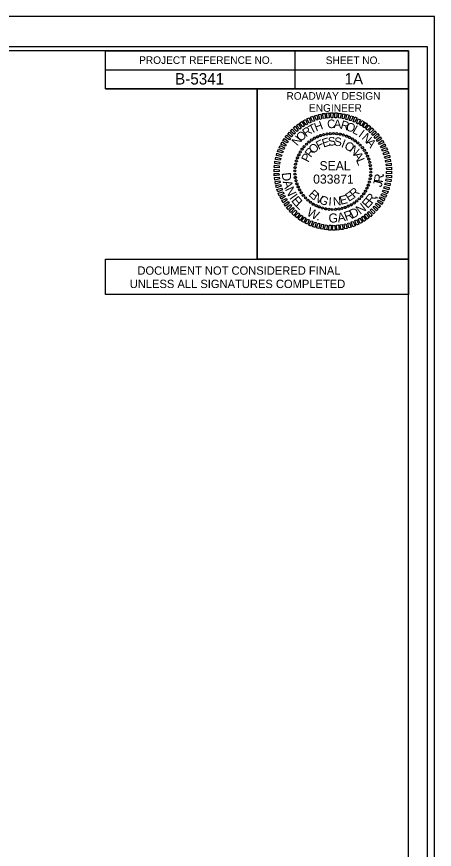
# Model space of a CAD drawing. Extents: x 1974126 to 1975810, y 438878 to 442173.
# Drawn here: x 1975533 to 1975809, y 441624 to 442173 of the extents above; entities that cross this region are included whole.
import ezdxf

# ---------------------------------------------------------------- set-up
doc = ezdxf.new("R2010")
doc.units = 0
for name, color, linetype in [('Sheet Cutting Line CELL', 7, 'Continuous'), ('Sheet Data Field CELL', 7, 'Continuous'), ('Sheet Plan CELL', 7, 'Continuous'), ('Sheet Plot Border Inside CELL', 7, 'Continuous'), ('Sheet Plot Border Outside CELL', 7, 'Continuous'), ('Sheet Professional Seal CELL', 7, 'Continuous'), ('Sheet Sticker Exception Certification CELL', 7, 'Continuous')]:
    doc.layers.add(name, color=color, linetype=linetype)

msp = doc.modelspace()

# ---------------------------------------------------------------- linework, layer by layer
at = {"layer": 'Sheet Cutting Line CELL'}
msp.add_line((1975809.14, 442173.29), (1974125.64, 442173.29), dxfattribs=at)
at = {"layer": 'Sheet Plan CELL'}
for p, q in [((1975717.14, 442150.74), (1975717.14, 442125.74)), ((1975592.09, 442138.24), (1975792.14, 442138.24)), ((1975592.09, 442125.74), (1975792.14, 442125.74)), ((1975592.09, 442125.74), (1975792.14, 442125.74)), ((1975692.14, 442125.74), (1975692.14, 442013.29))]:
    msp.add_line(p, q, dxfattribs=at)
for points in [[(1975792.14, 442150.79), (1974292.14, 442150.79), (1974292.14, 441100.79), (1975792.14, 441100.79)], [(1975592.09, 442150.79), (1975792.14, 442150.79), (1975792.14, 442125.74), (1975592.09, 442125.74)], [(1975692.14, 442125.74), (1975792.14, 442125.74), (1975792.14, 442013.24), (1975692.14, 442013.24)]]:
    msp.add_lwpolyline(points, close=True, dxfattribs=at)
at = {"layer": 'Sheet Plot Border Inside CELL'}
msp.add_lwpolyline([(1974138.64, 441098.29), (1975804.64, 441098.29), (1975804.64, 442153.29), (1974138.64, 442153.29)], close=True, dxfattribs=at)
at = {"layer": 'Sheet Plot Border Outside CELL'}
msp.add_lwpolyline([(1974125.64, 441078.29), (1975809.14, 441078.29), (1975809.14, 442173.29), (1974125.64, 442173.29)], close=True, dxfattribs=at)
at = {"layer": 'Sheet Professional Seal CELL'}
for p, q in [((1975733.96, 442094.8), (1975733.96, 442094.8)), ((1975736.06, 442095.4), (1975736.06, 442095.4)), ((1975738.26, 442095.8), (1975738.26, 442095.8)), ((1975740.41, 442096.1), (1975740.41, 442096.1)), ((1975742.61, 442096.15), (1975742.61, 442096.15)), ((1975744.81, 442096), (1975744.81, 442096)), ((1975746.96, 442095.65), (1975746.96, 442095.65)), ((1975749.06, 442095.2), (1975749.06, 442095.2)), ((1975751.16, 442094.5), (1975751.16, 442094.5)), ((1975724.71, 442089.1), (1975724.71, 442089.1)), ((1975726.36, 442090.6), (1975726.36, 442090.6)), ((1975728.11, 442091.85), (1975728.11, 442091.85)), ((1975730.01, 442093), (1975730.01, 442093)), ((1975731.96, 442094), (1975731.96, 442094)), ((1975753.16, 442093.6), (1975753.16, 442093.6)), ((1975755.11, 442092.6), (1975755.11, 442092.6)), ((1975756.91, 442091.35), (1975756.91, 442091.35)), ((1975758.66, 442090), (1975758.66, 442090)), ((1975720.61, 442084), (1975720.61, 442084)), ((1975721.86, 442085.8), (1975721.86, 442085.8)), ((1975723.21, 442087.55), (1975723.21, 442087.55)), ((1975760.21, 442088.5), (1975760.21, 442088.5)), ((1975761.71, 442086.85), (1975761.71, 442086.85)), ((1975762.96, 442085.1), (1975762.96, 442085.1)), ((1975764.11, 442083.2), (1975764.11, 442083.2)), ((1975718.01, 442077.95), (1975718.01, 442077.95)), ((1975718.71, 442080.05), (1975718.71, 442080.05)), ((1975719.61, 442082.05), (1975719.61, 442082.05)), ((1975765.11, 442081.25), (1975765.11, 442081.25)), ((1975765.91, 442079.25), (1975765.91, 442079.25)), ((1975717.21, 442073.7), (1975717.21, 442073.7)), ((1975717.56, 442075.85), (1975717.56, 442075.85)), ((1975766.51, 442077.15), (1975766.51, 442077.15)), ((1975766.91, 442074.95), (1975766.91, 442074.95)), ((1975767.21, 442072.8), (1975767.21, 442072.8)), ((1975717.06, 442071.5), (1975717.06, 442071.5)), ((1975717.11, 442069.3), (1975717.11, 442069.3)), ((1975717.41, 442067.15), (1975717.41, 442067.15)), ((1975742.16, 442071.05), (1975742.16, 442071.05)), ((1975767.11, 442068.4), (1975767.11, 442068.4)), ((1975767.26, 442070.6), (1975767.26, 442070.6)), ((1975717.81, 442064.95), (1975717.81, 442064.95)), ((1975718.41, 442062.85), (1975718.41, 442062.85)), ((1975765.61, 442062.05), (1975765.61, 442062.05)), ((1975766.31, 442064.15), (1975766.31, 442064.15)), ((1975766.76, 442066.25), (1975766.76, 442066.25)), ((1975719.21, 442060.85), (1975719.21, 442060.85)), ((1975720.21, 442058.9), (1975720.21, 442058.9)), ((1975721.36, 442057), (1975721.36, 442057)), ((1975762.46, 442056.3), (1975762.46, 442056.3)), ((1975763.71, 442058.1), (1975763.71, 442058.1)), ((1975764.71, 442060.05), (1975764.71, 442060.05)), ((1975722.61, 442055.25), (1975722.61, 442055.25)), ((1975724.11, 442053.6), (1975724.11, 442053.6)), ((1975725.66, 442052.1), (1975725.66, 442052.1)), ((1975727.41, 442050.75), (1975727.41, 442050.75)), ((1975756.21, 442050.25), (1975756.21, 442050.25)), ((1975757.96, 442051.5), (1975757.96, 442051.5)), ((1975759.61, 442053), (1975759.61, 442053)), ((1975761.11, 442054.55), (1975761.11, 442054.55)), ((1975729.21, 442049.5), (1975729.21, 442049.5)), ((1975731.16, 442048.5), (1975731.16, 442048.5)), ((1975733.16, 442047.6), (1975733.16, 442047.6)), ((1975735.26, 442046.9), (1975735.26, 442046.9)), ((1975737.36, 442046.45), (1975737.36, 442046.45)), ((1975739.51, 442046.1), (1975739.51, 442046.1)), ((1975741.71, 442045.95), (1975741.71, 442045.95)), ((1975743.91, 442046), (1975743.91, 442046)), ((1975746.06, 442046.3), (1975746.06, 442046.3)), ((1975748.26, 442046.7), (1975748.26, 442046.7)), ((1975750.36, 442047.3), (1975750.36, 442047.3)), ((1975752.36, 442048.1), (1975752.36, 442048.1)), ((1975754.31, 442049.1), (1975754.31, 442049.1))]:
    msp.add_line(p, q, dxfattribs=at)
for points in [[(1975724.46, 442101.8), (1975722.61, 442104.5), (1975724.16, 442105.3), (1975725.41, 442102.4)], [(1975726.61, 442103), (1975725.01, 442105.8), (1975726.56, 442106.5), (1975727.71, 442103.45)], [(1975728.81, 442104.05), (1975727.51, 442106.95), (1975729.01, 442107.55), (1975730.06, 442104.35)], [(1975731.26, 442104.85), (1975730.11, 442107.85), (1975731.66, 442108.3), (1975732.31, 442105.2)], [(1975733.66, 442105.5), (1975732.61, 442108.65), (1975734.31, 442109), (1975734.71, 442105.75)], [(1975736.06, 442106.05), (1975735.26, 442109.25), (1975736.91, 442109.4), (1975737.26, 442106.2)], [(1975738.46, 442106.35), (1975737.91, 442109.55), (1975739.61, 442109.75), (1975739.66, 442106.5)], [(1975740.96, 442106.6), (1975740.71, 442109.85), (1975742.36, 442109.8), (1975742.16, 442106.55)], [(1975743.36, 442106.55), (1975743.36, 442109.8), (1975745.01, 442109.75), (1975744.56, 442106.5)], [(1975745.86, 442106.4), (1975746.06, 442109.65), (1975747.71, 442109.35), (1975747.06, 442106.2)], [(1975748.26, 442106), (1975748.71, 442109.2), (1975750.36, 442108.95), (1975749.46, 442105.85)], [(1975750.81, 442105.45), (1975751.31, 442108.7), (1975753.01, 442108.3), (1975751.86, 442105.2)], [(1975753.21, 442104.8), (1975753.96, 442107.9), (1975755.51, 442107.4), (1975754.26, 442104.45)], [(1975755.46, 442103.9), (1975756.61, 442107.05), (1975758.01, 442106.45), (1975756.61, 442103.55)], [(1975757.71, 442102.95), (1975758.96, 442105.9), (1975760.51, 442105.2), (1975758.81, 442102.4)], [(1975718.36, 442097.5), (1975716.16, 442099.7), (1975717.36, 442100.9), (1975719.31, 442098.2)], [(1975720.36, 442099.05), (1975718.21, 442101.45), (1975719.56, 442102.5), (1975721.31, 442099.7)], [(1975722.26, 442100.55), (1975720.41, 442103.1), (1975721.71, 442104.05), (1975723.36, 442101.15)], [(1975760.01, 442101.8), (1975761.36, 442104.65), (1975762.86, 442103.8), (1975760.96, 442101.2)], [(1975761.96, 442100.45), (1975763.71, 442103.35), (1975765.01, 442102.3), (1975763.06, 442099.85)], [(1975764.01, 442098.95), (1975765.86, 442101.7), (1975767.16, 442100.6), (1975764.96, 442098.25)], [(1975765.91, 442097.4), (1975767.96, 442100), (1975769.16, 442098.8), (1975766.86, 442096.65)], [(1975713.46, 442091.95), (1975710.76, 442093.65), (1975711.71, 442095.1), (1975714.11, 442092.9)], [(1975714.96, 442093.85), (1975712.36, 442095.8), (1975713.46, 442097.1), (1975715.66, 442094.75)], [(1975716.71, 442095.75), (1975714.16, 442097.8), (1975715.41, 442098.95), (1975717.51, 442096.55)], [(1975767.71, 442095.65), (1975769.86, 442098), (1975771.06, 442096.8), (1975768.46, 442094.85)], [(1975769.46, 442093.85), (1975771.76, 442096.1), (1975772.81, 442094.75), (1975770.16, 442092.85)], [(1975710.76, 442087.8), (1975707.91, 442089.05), (1975708.66, 442090.6), (1975711.36, 442088.75)], [(1975711.96, 442089.95), (1975709.16, 442091.45), (1975710.16, 442092.85), (1975712.76, 442090.85)], [(1975770.96, 442091.9), (1975773.41, 442094), (1975774.36, 442092.55), (1975771.56, 442090.95)], [(1975772.26, 442089.85), (1975774.91, 442091.75), (1975775.86, 442090.25), (1975772.96, 442088.85)], [(1975773.56, 442087.65), (1975776.36, 442089.4), (1975777.01, 442087.85), (1975774.16, 442086.7)], [(1975708.01, 442080.9), (1975704.91, 442081.55), (1975705.26, 442083.2), (1975708.41, 442081.95)], [(1975708.76, 442083.3), (1975705.66, 442084.2), (1975706.31, 442085.75), (1975709.31, 442084.35)], [(1975709.76, 442085.5), (1975706.66, 442086.65), (1975707.41, 442088.2), (1975710.26, 442086.6)], [(1975774.56, 442085.5), (1975777.51, 442087), (1975778.16, 442085.4), (1975775.06, 442084.4)], [(1975775.46, 442083.15), (1975778.51, 442084.45), (1975779.06, 442082.9), (1975775.96, 442082.1)], [(1975706.96, 442075.95), (1975703.76, 442076.25), (1975703.96, 442077.95), (1975707.21, 442077.15)], [(1975707.36, 442078.5), (1975704.26, 442078.9), (1975704.61, 442080.6), (1975707.76, 442079.55)], [(1975776.26, 442080.75), (1975779.46, 442081.9), (1975779.76, 442080.25), (1975776.61, 442079.7)], [(1975776.86, 442078.35), (1975780.01, 442079.3), (1975780.31, 442077.6), (1975777.16, 442077.3)], [(1975706.66, 442071.05), (1975703.41, 442070.9), (1975703.41, 442072.6), (1975706.66, 442072.25)], [(1975706.71, 442073.55), (1975703.46, 442073.65), (1975703.56, 442075.3), (1975706.81, 442074.75)], [(1975777.31, 442075.95), (1975780.56, 442076.65), (1975780.71, 442074.95), (1975777.51, 442074.75)], [(1975777.61, 442073.55), (1975780.86, 442073.95), (1975780.96, 442072.25), (1975777.71, 442072.35)], [(1975706.71, 442068.55), (1975703.46, 442068.15), (1975703.36, 442069.85), (1975706.61, 442069.75)], [(1975707.01, 442066.15), (1975703.76, 442065.45), (1975703.61, 442067.15), (1975706.81, 442067.35)], [(1975777.61, 442068.55), (1975780.86, 442068.45), (1975780.76, 442066.8), (1975777.51, 442067.35)], [(1975777.66, 442071.05), (1975780.91, 442071.2), (1975780.91, 442069.5), (1975777.66, 442069.85)], [(1975707.46, 442063.75), (1975704.31, 442062.8), (1975704.01, 442064.5), (1975707.16, 442064.8)], [(1975708.06, 442061.35), (1975704.86, 442060.2), (1975704.56, 442061.85), (1975707.71, 442062.4)], [(1975776.31, 442061.2), (1975779.41, 442060.55), (1975779.06, 442058.9), (1975775.91, 442060.15)], [(1975776.96, 442063.6), (1975780.06, 442063.2), (1975779.71, 442061.5), (1975776.56, 442062.55)], [(1975777.36, 442066.15), (1975780.56, 442065.85), (1975780.36, 442064.15), (1975777.11, 442064.95)], [(1975708.86, 442058.95), (1975705.81, 442057.65), (1975705.26, 442059.2), (1975708.36, 442060)], [(1975709.76, 442056.6), (1975706.81, 442055.1), (1975706.16, 442056.7), (1975709.26, 442057.7)], [(1975774.56, 442056.6), (1975777.66, 442055.45), (1975776.91, 442053.9), (1975774.06, 442055.5)], [(1975775.56, 442058.8), (1975778.66, 442057.9), (1975778.01, 442056.35), (1975775.01, 442057.75)], [(1975710.76, 442054.45), (1975707.96, 442052.7), (1975707.31, 442054.25), (1975710.16, 442055.4)], [(1975712.06, 442052.25), (1975709.41, 442050.35), (1975708.46, 442051.85), (1975711.36, 442053.25)], [(1975713.36, 442050.2), (1975710.91, 442048.1), (1975709.96, 442049.55), (1975712.76, 442051.15)], [(1975770.86, 442050.15), (1975773.56, 442048.45), (1975772.61, 442047), (1975770.21, 442049.2)], [(1975772.36, 442052.15), (1975775.16, 442050.65), (1975774.16, 442049.25), (1975771.56, 442051.25)], [(1975773.56, 442054.3), (1975776.41, 442053.05), (1975775.66, 442051.5), (1975772.96, 442053.35)], [(1975714.86, 442048.25), (1975712.56, 442046), (1975711.51, 442047.35), (1975714.16, 442049.25)], [(1975716.61, 442046.45), (1975714.46, 442044.1), (1975713.26, 442045.3), (1975715.86, 442047.25)], [(1975718.41, 442044.7), (1975716.36, 442042.1), (1975715.16, 442043.3), (1975717.46, 442045.45)], [(1975765.96, 442044.6), (1975768.16, 442042.4), (1975766.96, 442041.2), (1975765.01, 442043.9)], [(1975767.61, 442046.35), (1975770.16, 442044.3), (1975768.91, 442043.15), (1975766.81, 442045.55)], [(1975769.36, 442048.25), (1975771.96, 442046.3), (1975770.86, 442045), (1975768.66, 442047.35)], [(1975720.31, 442043.15), (1975718.46, 442040.4), (1975717.16, 442041.5), (1975719.36, 442043.85)], [(1975722.36, 442041.65), (1975720.61, 442038.75), (1975719.31, 442039.8), (1975721.26, 442042.25)], [(1975724.31, 442040.3), (1975722.96, 442037.45), (1975721.46, 442038.3), (1975723.36, 442040.9)], [(1975726.61, 442039.15), (1975725.36, 442036.2), (1975723.81, 442036.9), (1975725.51, 442039.7)], [(1975757.71, 442039.1), (1975759.31, 442036.3), (1975757.76, 442035.6), (1975756.61, 442038.65)], [(1975759.86, 442040.3), (1975761.71, 442037.6), (1975760.16, 442036.8), (1975758.91, 442039.7)], [(1975762.06, 442041.55), (1975763.91, 442039), (1975762.61, 442038.05), (1975760.96, 442040.95)], [(1975763.96, 442043.05), (1975766.11, 442040.65), (1975764.76, 442039.6), (1975763.01, 442042.4)], [(1975728.86, 442038.2), (1975727.71, 442035.05), (1975726.31, 442035.65), (1975727.71, 442038.55)], [(1975731.11, 442037.3), (1975730.36, 442034.2), (1975728.81, 442034.7), (1975730.06, 442037.65)], [(1975733.51, 442036.65), (1975733.01, 442033.4), (1975731.31, 442033.8), (1975732.46, 442036.9)], [(1975736.06, 442036.1), (1975735.61, 442032.9), (1975733.96, 442033.15), (1975734.86, 442036.25)], [(1975738.46, 442035.7), (1975738.26, 442032.45), (1975736.61, 442032.75), (1975737.26, 442035.9)], [(1975740.96, 442035.55), (1975740.96, 442032.3), (1975739.31, 442032.35), (1975739.76, 442035.6)], [(1975743.36, 442035.5), (1975743.61, 442032.25), (1975741.96, 442032.3), (1975742.16, 442035.55)], [(1975745.86, 442035.75), (1975746.41, 442032.55), (1975744.71, 442032.35), (1975744.66, 442035.6)], [(1975748.26, 442036.05), (1975749.06, 442032.85), (1975747.41, 442032.7), (1975747.06, 442035.9)], [(1975750.66, 442036.6), (1975751.71, 442033.45), (1975750.01, 442033.1), (1975749.61, 442036.35)], [(1975753.06, 442037.25), (1975754.21, 442034.25), (1975752.66, 442033.8), (1975752.01, 442036.9)], [(1975755.51, 442038.05), (1975756.81, 442035.15), (1975755.31, 442034.55), (1975754.26, 442037.75)]]:
    msp.add_lwpolyline(points, close=True, dxfattribs=at)
for centre, major_axis in [((1975731.96, 442093.97), (-0.293, 0.658)), ((1975734, 442094.77), (-0.234, 0.681)), ((1975736.09, 442095.39), (-0.174, 0.699)), ((1975738.24, 442095.83), (-0.113, 0.711)), ((1975740.41, 442096.07), (-0.05, 0.718)), ((1975742.6, 442096.13), (0.013, 0.72)), ((1975744.78, 442096), (0.075, 0.716)), ((1975746.95, 442095.67), (0.137, 0.707)), ((1975749.07, 442095.16), (0.198, 0.692)), ((1975751.15, 442094.47), (0.258, 0.672)), ((1975753.16, 442093.6), (0.316, 0.647)), ((1975724.74, 442089.09), (-0.5, 0.518)), ((1975726.38, 442090.54), (-0.453, 0.56)), ((1975728.14, 442091.85), (-0.403, 0.597)), ((1975730, 442092.99), (-0.349, 0.63)), ((1975755.08, 442092.55), (0.371, 0.617)), ((1975756.9, 442091.34), (0.423, 0.582)), ((1975758.61, 442089.98), (0.472, 0.543)), ((1975760.2, 442088.48), (0.518, 0.5)), ((1975720.66, 442083.97), (-0.617, 0.371)), ((1975721.87, 442085.8), (-0.582, 0.423)), ((1975723.23, 442087.51), (-0.543, 0.472)), ((1975761.65, 442086.84), (0.56, 0.453)), ((1975762.95, 442085.08), (0.597, 0.403)), ((1975764.1, 442083.21), (0.63, 0.349)), ((1975718.05, 442077.97), (-0.692, 0.198)), ((1975718.75, 442080.04), (-0.672, 0.258)), ((1975719.62, 442082.05), (-0.647, 0.316)), ((1975765.07, 442081.25), (0.658, 0.293)), ((1975765.87, 442079.22), (0.681, 0.234)), ((1975766.5, 442077.12), (0.699, 0.174)), ((1975717.08, 442071.49), (-0.72, 0.013)), ((1975717.22, 442073.68), (-0.716, 0.075)), ((1975717.54, 442075.84), (-0.707, 0.137)), ((1975766.93, 442074.98), (0.711, 0.113)), ((1975767.18, 442072.8), (0.718, 0.05)), ((1975717.14, 442069.3), (-0.718, -0.05)), ((1975717.39, 442067.13), (-0.711, -0.113)), ((1975766.78, 442066.27), (0.707, -0.137)), ((1975767.1, 442068.43), (0.716, -0.075)), ((1975767.24, 442070.62), (0.72, -0.013)), ((1975717.83, 442064.99), (-0.699, -0.174)), ((1975718.45, 442062.89), (-0.681, -0.234)), ((1975719.25, 442060.85), (-0.658, -0.293)), ((1975765.57, 442062.07), (0.672, -0.258)), ((1975766.27, 442064.14), (0.692, -0.198)), ((1975720.23, 442058.89), (-0.63, -0.349)), ((1975721.37, 442057.03), (-0.597, -0.403)), ((1975722.67, 442055.27), (-0.56, -0.453)), ((1975762.45, 442056.31), (0.582, -0.423)), ((1975763.66, 442058.14), (0.617, -0.371)), ((1975764.7, 442060.06), (0.647, -0.316)), ((1975724.12, 442053.63), (-0.518, -0.5)), ((1975725.71, 442052.13), (-0.472, -0.543)), ((1975727.42, 442050.76), (-0.423, -0.582)), ((1975729.24, 442049.56), (-0.371, -0.617)), ((1975756.19, 442050.26), (0.403, -0.597)), ((1975757.94, 442051.56), (0.453, -0.56)), ((1975759.58, 442053.01), (0.5, -0.518)), ((1975761.09, 442054.6), (0.543, -0.472)), ((1975731.17, 442048.51), (-0.316, -0.647)), ((1975733.17, 442047.64), (-0.258, -0.672)), ((1975735.25, 442046.95), (-0.198, -0.692)), ((1975737.38, 442046.43), (-0.137, -0.707)), ((1975739.54, 442046.11), (-0.075, -0.716)), ((1975741.72, 442045.98), (-0.013, -0.72)), ((1975743.91, 442046.03), (0.05, -0.718)), ((1975746.08, 442046.28), (0.113, -0.711)), ((1975748.23, 442046.72), (0.174, -0.699)), ((1975750.33, 442047.34), (0.234, -0.681)), ((1975752.36, 442048.14), (0.293, -0.658)), ((1975754.32, 442049.12), (0.349, -0.63))]:
    msp.add_ellipse(centre, major_axis=major_axis, ratio=0.999708, dxfattribs=at)
at = {"layer": 'Sheet Sticker Exception Certification CELL'}
for p, q in [((1975592.11, 441989.76), (1975592.11, 442013.26)), ((1975592.11, 442013.26), (1975792.14, 442013.26)), ((1975792.14, 442013.24), (1975792.14, 441989.74)), ((1975792.14, 441989.76), (1975592.11, 441989.76))]:
    msp.add_line(p, q, dxfattribs=at)

# ---------------------------------------------------------------- texts
at = {"layer": 'Sheet Data Field CELL'}
for s, p in [('B-5341', (1975638.06, 442128.49)), ('1A', (1975749.86, 442128.54))]:
    msp.add_text(s, height=7.5, dxfattribs=at).set_placement(p)
at = {"layer": 'Sheet Plan CELL'}
for s, height, p in [('PROJECT REFERENCE NO.', 5.0001, (1975614.29, 442142.09)), ('SHEET NO.', 5, (1975737.44, 442141.99)), ('ROADWAY DESIGN', 5.0001, (1975711.54, 442118.44)), ('ENGINEER', 5, (1975726.39, 442110.49))]:
    msp.add_text(s, height=height, dxfattribs=at).set_placement(p)
at = {"layer": 'Sheet Professional Seal CELL'}
for s, height, rotation, p in [('C', 5.64, 6.2199, (1975738.71, 442099.4)), ('A', 5.64, 359.0203, (1975742.66, 442099.7)), ('R', 5.64, 35.0205, (1975724.46, 442093.55)), ('T', 5.64, 27.8198, (1975727.86, 442095.75)), ('H', 5.64, 20.6195, (1975731.11, 442097.4)), ('R', 5.64, 344.6211, (1975746.86, 442099.5)), ('O', 5.64, 337.4212, (1975750.21, 442098.75)), ('L', 5.64, 330.2209, (1975754.61, 442096.9)), ('N', 5.64, 49.4235, (1975718.71, 442087.55)), ('O', 5.64, 42.2217, (1975721.01, 442090.45)), ('S', 5.64, 7.2556, (1975739.36, 442087.9)), ('I', 5.64, 323.0201, (1975758.66, 442094.5)), ('N', 5.64, 315.8189, (1975760.81, 442092.95)), ('O', 5.64, 44.6812, (1975729.41, 442082.4)), ('F', 5.64, 25.967, (1975732.71, 442085.35)), ('E', 5.64, 16.6111, (1975735.91, 442086.85)), ('S', 5.64, 357.9004, (1975742.96, 442087.95)), ('I', 5.64, 339.1896, (1975747.26, 442087.25)), ('O', 5.64, 329.8335, (1975749.26, 442086.55)), ('A', 5.64, 308.6172, (1975763.76, 442090)), ('P', 5.64, 63.3989, (1975726.06, 442076.75)), ('R', 5.64, 54.0397, (1975727.66, 442079.95)), ('N', 5.64, 320.4766, (1975752.61, 442084.55)), ('A', 5.64, 301.7603, (1975755.46, 442081.95)), ('SEAL', 5.998, 360, (1975733.36, 442071.9)), ('L', 5.64, 292.4008, (1975757.41, 442078.5)), ('D', 6, 276.5178, (1975708.35, 442070.11)), ('R', 6, 81.8439, (1975775.11, 442063.4)), ('.', 6, 89.3242, (1975775.82, 442067.75)), ('A', 6, 286.3936, (1975709.01, 442064.33)), ('N', 6, 295.2339, (1975710.44, 442059.31)), ('J', 6, 76.5861, (1975774.27, 442060.41)), ('I', 6, 305.9598, (1975713.18, 442053.62)), ('E', 5.64, 318.2769, (1975725.76, 442055.4)), ('N', 5.64, 327.634, (1975728.76, 442052.7)), ('E', 5.64, 14.4118, (1975747.41, 442049)), ('E', 5.64, 33.1241, (1975752.71, 442050.95)), ('R', 5.64, 42.4814, (1975756.26, 442053.3)), ('R', 6, 54.8717, (1975768.05, 442049.29)), ('E', 6, 309.7617, (1975714.4, 442051.73)), ('L', 6, 316.871, (1975717, 442048.44)), ('G', 5.64, 336.9902, (1975732.56, 442050.45)), ('I', 5.64, 355.7012, (1975739.11, 442048.55)), ('N', 5.64, 5.0564, (1975742.46, 442048.4)), ('N', 6, 37.0366, (1975760.14, 442042.4)), ('E', 6, 47.7624, (1975765.16, 442046.25)), (',', 6, 62.352, (1975770.67, 442052.84)), ('W', 6, 333.3462, (1975724.45, 442042.24)), ('R', 6, 19.6805, (1975750.78, 442038.34)), ('D', 6, 27.1608, (1975754.96, 442039.74)), ('.', 6, 345.8802, (1975731.12, 442039.08)), ('G', 6, 0.1144, (1975739.32, 442037.35)), ('A', 6, 10.8402, (1975745.65, 442037.41))]:
    msp.add_text(s, height=height, rotation=rotation, dxfattribs=at).set_placement(p)
msp.add_text('033871', height=5.998, dxfattribs=at).set_placement((1975729.19, 442063.05))
at = {"layer": 'Sheet Sticker Exception Certification CELL'}
for s, p in [('DOCUMENT NOT CONSIDERED FINAL', (1975613.18, 442002.91)), ('UNLESS ALL SIGNATURES COMPLETED', (1975608.11, 441994.11))]:
    msp.add_text(s, height=5.5, dxfattribs=at).set_placement(p)

doc.saveas('drawing.dxf')
